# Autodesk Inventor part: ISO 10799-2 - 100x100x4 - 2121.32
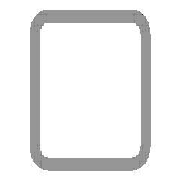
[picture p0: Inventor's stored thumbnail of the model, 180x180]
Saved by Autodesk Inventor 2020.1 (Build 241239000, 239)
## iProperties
Created: 2019-10
Part Number: ISO 10799-2 - 100x100x4 - 2121.32
Material: Stainless Steel
Description: Structural steels - Cold-formed, welded, structural hollow sections
Document SubType Name: Modeling
Standard: ISO
Designer: Synergysoft Dell02
Standard Revision: First edition 2011-09-15
Standards Organization: ISO
Language: en-US
Size Designation: 100x100x4
Categories: <MemberInstance><Categories><Category DisplayName="Structural Shapes" InternalName="089c4875-fa83-4c05-b084-43b9cc11f5ed" Mnemonic="GRDR"><CategoryParameter Dis
Stock Number: 100x100x4
Density: 8 g/cm^3
Appearance: Semi-Polished
_CCFamilyMember: 43
_CCFamilyDisplayName: ISO 10799-2 (Square) - Structural steels - Cold-formed, welded, structural hollow sections
_FrameMemberDoc: Frame Member File
_Version: 15.0.0
_GetPNFromCC: 1
G_L: 2121.320 mm
G_W: 100.000 mm
G_H: 100.000 mm
IsCustomPart: 1
Author: Synergysoft Dell02
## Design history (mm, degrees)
node "Start Plane"
node "End Plane"
sketch "Sketch"
  geometry: L1 (-50, -42)-(-50, 42); L2 (-42, 50)-(42, 50); L3 (50, 42)-(50, -42); L4 (42, -50)-(-42, -50); L5 (-42, 46)-(42, 46); L6 (46, 42)-(46, -42); L7 (42, -46)-(-42, -46); L8 (-46, -42)-(-46, 42); L9 (0, 72.32)-(0, -72.32) reference; L10 (-72.32, 0)-(72.32, 0) reference; A1 r 8 centre (-42, -42) between (-50, -42) and (-42, -50); A2 r 8 centre (42, 42) between (50, 42) and (42, 50); A3 r 8 centre (-42, 42) between (-42, 50) and (-50, 42); A4 r 8 centre (42, -42) between (42, -50) and (50, -42); A5 r 4 centre (-42, 42) between (-42, 46) and (-46, 42); A6 r 4 centre (42, 42) between (46, 42) and (42, 46); A7 r 4 centre (42, -42) between (42, -46) and (46, -42); A8 r 4 centre (-42, -42) between (-46, -42) and (-42, -46)
  constraints: 16 end point, 16 point on circle, 8 centre point, 8 tangent, 4 parallel, 3 equal radius, 2 perpendicular, 7 other
  dimensions: "d7" = 8 radius of A1 (= G_IR); "d9" = 100 distance between parallel lines of L1 L3 (= G_W); "d11" = 100 distance between parallel lines of L2 L4 (= G_H); "d12" = 4 distance between parallel lines of L3 L6 (= G_T); "d15" = 50 distance between parallel lines of L9 L3 (= 0.5 x d9); "d16" = 50 distance between parallel lines of L2 L10 (= 0.5 x d11)
extrude "Body" new body sketch "Sketch" stored distance "d3" = 2121.32034 (= G_L); taper "d4" = 0 deg
node "Driven Length"
  sketch "Sketch3"
    geometry: L1 (0, 0)-(10, 0) reference
    constraints: 2 end point, 1 horizontal
  workplane "Work Plane3"
  sketch "Sketch4"
    geometry: L1 (-2, 0)-(12, 0) reference; L2 (-2, 2121.32)-(12, 2121.32) reference
    dimensions: "d18" = 2121.32034 distance between parallel lines of L1 L2 (derived)
body "Solid1"
other parameters: "G_W" = 100 [user parameter; used in 1 equation term], "G_H" = 100 [user parameter; used in 1 equation term], "G_T" = 4 [user parameter; used in 1 equation term], "G_IR" = 8 [user parameter; used in 1 equation term], "G_L" = 2121.32034 (= d18) [user parameter; used in 1 equation term], "G_OFFSET_START" = 0 [user parameter; used in 1 equation term], "G_OFFSET_END" = 0 [user parameter; used in 1 equation term], "d13" = 0 (computed from G_OFFSET_START), "d14" = 2121.32034 (= G_OFFSET_END + B_L), "B_L" = 2121.32034 [user parameter; used in 1 equation term], "d17" = 90 deg, "MAS" = 1.17 [user parameter]
